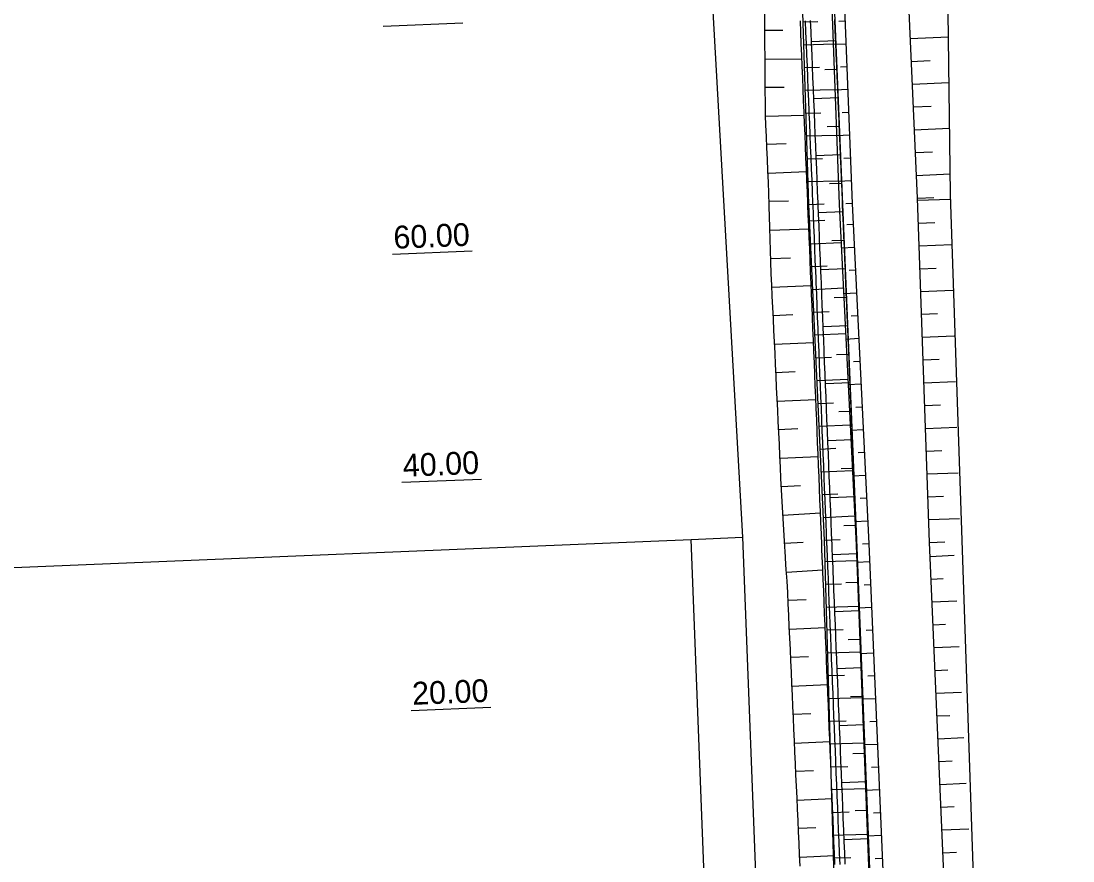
# Model space of a CAD drawing. Extents: x -583721 to -583071, y -1166145 to -1165065.
# Drawn here: x -583294.2 to -583202, y -1165823.5 to -1165749.9 of the extents above; entities that cross this region are included whole.
import ezdxf

# ---------------------------------------------------------------- set-up
doc = ezdxf.new("R2010")
doc.units = 0
for name, color, linetype in [('01_DOPRAVA', 7, 'Continuous'), ('14', 7, 'Continuous'), ('21', 7, 'Continuous'), ('_Rozpiska', 7, 'Continuous'), ('KOTY', 7, 'Continuous'), ('Popis cest', 7, 'Continuous'), ('Popis PP', 7, 'Continuous'), ('Rámy', 7, 'Continuous'), ('Trojúhelniky', 7, 'Continuous')]:
    doc.layers.add(name, color=color, linetype=linetype)

msp = doc.modelspace()

# ---------------------------------------------------------------- linework, layer by layer
at = {"layer": '01_DOPRAVA'}
for p, q in [((-583387, -1165801.65), (-583235.49, -1165795.36)), ((-583235.49, -1165795.36), (-583230.99, -1165795.18))]:
    msp.add_line(p, q, dxfattribs=at)
for points in [[(-583374.25, -1165656.58), (-583351.23, -1165657.59), (-583331.17, -1165652.35), (-583245.16, -1165665.31), (-583236.84, -1165691.62), (-583230.99, -1165795.18)], [(-583228.69, -1165666.2), (-583226.21, -1165672.99), (-583225.84, -1165679.92), (-583220.97, -1165796.08), (-583216.51, -1165909.44), (-583213.19, -1165995.13), (-583203.41, -1165993.97)], [(-583206.76, -1165905.62), (-583208.9, -1165862.71), (-583209.34, -1165848.45), (-583210.45, -1165834.4), (-583212.79, -1165765.14), (-583213.22, -1165730.9), (-583214.03, -1165712.42)], [(-583232.68, -1165868.31), (-583234.23, -1165827.88), (-583235.49, -1165795.36)], [(-583230.99, -1165795.18), (-583226.89, -1165901.72), (-583222.76, -1166003.69), (-583215.5, -1166006.52)]]:
    msp.add_lwpolyline(points, dxfattribs=at)
at = {"layer": '14'}
for p, q in [((-583227.47, -1165750.761), (-583229.042, -1165750.773)), ((-583224.957, -1165751.73), (-583222.833, -1165751.643)), ((-583229.023, -1165753.273), (-583225.796, -1165753.248)), ((-583223.791, -1165754.184), (-583222.728, -1165754.141)), ((-583227.349, -1165755.759), (-583229.004, -1165755.773)), ((-583224.752, -1165756.726), (-583222.624, -1165756.639)), ((-583228.983, -1165758.273), (-583225.594, -1165758.182)), ((-583223.584, -1165759.18), (-583222.519, -1165759.137)), ((-583227.182, -1165760.696), (-583228.87, -1165760.77)), ((-583224.548, -1165761.722), (-583222.414, -1165761.634)), ((-583228.762, -1165763.268), (-583225.391, -1165763.135)), ((-583223.378, -1165764.176), (-583222.309, -1165764.132)), ((-583226.981, -1165765.708), (-583228.674, -1165765.766)), ((-583224.343, -1165766.718), (-583222.205, -1165766.63)), ((-583228.589, -1165768.265), (-583225.185, -1165768.156)), ((-583223.171, -1165769.172), (-583222.1, -1165769.128)), ((-583226.799, -1165770.708), (-583228.515, -1165770.764)), ((-583224.139, -1165771.713), (-583221.995, -1165771.626)), ((-583228.426, -1165773.262), (-583224.982, -1165773.119)), ((-583222.964, -1165774.167), (-583221.891, -1165774.123)), ((-583226.594, -1165775.678), (-583228.308, -1165775.759)), ((-583223.934, -1165776.709), (-583221.786, -1165776.621)), ((-583228.189, -1165778.256), (-583224.778, -1165778.095)), ((-583222.757, -1165779.163), (-583221.681, -1165779.119)), ((-583226.374, -1165780.673), (-583228.071, -1165780.754)), ((-583223.73, -1165781.705), (-583221.576, -1165781.617)), ((-583227.953, -1165783.251), (-583224.574, -1165783.091)), ((-583222.55, -1165784.159), (-583221.472, -1165784.115)), ((-583226.153, -1165785.668), (-583227.834, -1165785.748)), ((-583223.525, -1165786.701), (-583221.367, -1165786.612)), ((-583227.716, -1165788.245), (-583224.369, -1165788.087)), ((-583222.343, -1165789.154), (-583221.262, -1165789.11)), ((-583225.933, -1165790.658), (-583227.598, -1165790.742)), ((-583223.321, -1165791.697), (-583221.157, -1165791.608)), ((-583227.462, -1165793.239), (-583224.166, -1165793.047)), ((-583222.136, -1165794.15), (-583221.053, -1165794.106)), ((-583225.686, -1165795.632), (-583227.307, -1165795.734)), ((-583223.116, -1165796.692), (-583220.949, -1165796.604)), ((-583227.149, -1165798.229), (-583223.962, -1165798.034)), ((-583221.933, -1165799.146), (-583220.851, -1165799.102)), ((-583225.43, -1165800.643), (-583227.002, -1165800.724)), ((-583222.912, -1165801.688), (-583220.753, -1165801.6)), ((-583226.89, -1165803.222), (-583223.755, -1165803.081)), ((-583221.732, -1165804.142), (-583220.655, -1165804.098)), ((-583225.215, -1165805.649), (-583226.777, -1165805.719)), ((-583222.707, -1165806.684), (-583220.556, -1165806.596)), ((-583226.665, -1165808.217), (-583223.551, -1165808.077)), ((-583221.531, -1165809.138), (-583220.458, -1165809.094)), ((-583225.001, -1165810.645), (-583226.553, -1165810.714)), ((-583222.503, -1165811.68), (-583220.36, -1165811.592)), ((-583226.44, -1165813.212), (-583223.346, -1165813.073)), ((-583221.331, -1165814.134), (-583220.261, -1165814.09)), ((-583224.786, -1165815.64), (-583226.328, -1165815.709)), ((-583222.298, -1165816.676), (-583220.163, -1165816.588)), ((-583226.216, -1165818.207), (-583223.142, -1165818.068)), ((-583221.13, -1165819.13), (-583220.065, -1165819.086)), ((-583224.571, -1165820.635), (-583226.103, -1165820.704)), ((-583222.094, -1165821.671), (-583219.967, -1165821.584)), ((-583225.991, -1165823.202), (-583222.937, -1165823.064))]:
    msp.add_line(p, q, dxfattribs=at)
at = {"layer": '21'}
for points in [[(-583225.956, -1165823.988), (-583226.001, -1165822.989), (-583226.045, -1165821.99), (-583226.09, -1165820.991), (-583226.135, -1165819.992), (-583226.18, -1165818.993), (-583226.225, -1165817.994), (-583226.27, -1165816.995), (-583226.315, -1165815.996), (-583226.36, -1165814.997), (-583226.405, -1165813.998), (-583226.45, -1165812.999), (-583226.495, -1165812), (-583226.54, -1165811.001), (-583226.585, -1165810.002), (-583226.63, -1165809.003), (-583226.675, -1165808.004), (-583226.72, -1165807.005), (-583226.765, -1165806.006), (-583226.81, -1165805.007), (-583226.854, -1165804.008), (-583226.899, -1165803.009), (-583226.944, -1165802.01), (-583226.989, -1165801.011), (-583227.034, -1165800.012), (-583227.098, -1165799.014), (-583227.142, -1165798.334), (-583227.162, -1165798.015), (-583227.227, -1165797.017), (-583227.27, -1165796.338), (-583227.284, -1165796.111), (-583227.29, -1165796.019), (-583227.352, -1165795.021), (-583227.414, -1165794.022), (-583227.476, -1165793.024), (-583227.537, -1165792.026), (-583227.584, -1165791.027), (-583227.632, -1165790.028), (-583227.679, -1165789.029), (-583227.726, -1165788.03), (-583227.774, -1165787.031), (-583227.821, -1165786.032), (-583227.868, -1165785.033), (-583227.916, -1165784.035), (-583227.963, -1165783.036), (-583228.01, -1165782.037), (-583228.058, -1165781.038), (-583228.105, -1165780.039), (-583228.152, -1165779.04), (-583228.2, -1165778.041), (-583228.247, -1165777.042), (-583228.294, -1165776.043), (-583228.342, -1165775.044), (-583228.389, -1165774.046), (-583228.436, -1165773.047), (-583228.457, -1165772.604), (-583228.477, -1165772.047), (-583228.506, -1165771.048), (-583228.536, -1165770.048), (-583228.566, -1165769.049), (-583228.596, -1165768.049), (-583228.63, -1165767.05), (-583228.658, -1165766.24), (-583228.664, -1165766.05), (-583228.699, -1165765.051), (-583228.733, -1165764.051), (-583228.77, -1165763.052), (-583228.814, -1165762.053), (-583228.858, -1165761.054), (-583228.902, -1165760.055), (-583228.945, -1165759.056), (-583228.986, -1165758.207), (-583228.987, -1165758.057), (-583228.987, -1165758.031), (-583228.994, -1165757.056), (-583229.002, -1165756.056), (-583229.01, -1165755.055), (-583229.017, -1165754.055), (-583229.025, -1165753.054), (-583229.032, -1165752.053), (-583229.04, -1165751.053), (-583229.047, -1165750.052), (-583229.055, -1165749.052)], [(-583219.882, -1165823.739), (-583219.921, -1165822.74), (-583219.96, -1165821.741), (-583220, -1165820.741), (-583220.039, -1165819.742), (-583220.078, -1165818.743), (-583220.118, -1165817.744), (-583220.157, -1165816.745), (-583220.196, -1165815.745), (-583220.236, -1165814.746), (-583220.275, -1165813.747), (-583220.314, -1165812.748), (-583220.354, -1165811.748), (-583220.393, -1165810.749), (-583220.432, -1165809.75), (-583220.471, -1165808.751), (-583220.511, -1165807.752), (-583220.55, -1165806.752), (-583220.589, -1165805.753), (-583220.629, -1165804.754), (-583220.668, -1165803.755), (-583220.707, -1165802.755), (-583220.747, -1165801.756), (-583220.786, -1165800.757), (-583220.825, -1165799.758), (-583220.865, -1165798.758), (-583220.891, -1165798.079), (-583220.904, -1165797.759), (-583220.943, -1165796.76), (-583220.97, -1165796.08), (-583220.98, -1165795.853), (-583220.983, -1165795.761), (-583221.025, -1165794.762), (-583221.067, -1165793.763), (-583221.109, -1165792.763), (-583221.151, -1165791.764), (-583221.193, -1165790.765), (-583221.235, -1165789.766), (-583221.277, -1165788.767), (-583221.318, -1165787.768), (-583221.36, -1165786.769), (-583221.402, -1165785.77), (-583221.444, -1165784.77), (-583221.486, -1165783.771), (-583221.528, -1165782.772), (-583221.57, -1165781.773), (-583221.612, -1165780.774), (-583221.654, -1165779.775), (-583221.695, -1165778.776), (-583221.737, -1165777.777), (-583221.779, -1165776.777), (-583221.821, -1165775.778), (-583221.863, -1165774.779), (-583221.905, -1165773.78), (-583221.947, -1165772.781), (-583221.965, -1165772.338), (-583221.989, -1165771.782), (-583222.031, -1165770.783), (-583222.072, -1165769.784), (-583222.114, -1165768.784), (-583222.156, -1165767.785), (-583222.198, -1165766.786), (-583222.232, -1165765.977), (-583222.24, -1165765.787), (-583222.282, -1165764.788), (-583222.324, -1165763.789), (-583222.366, -1165762.79), (-583222.408, -1165761.791), (-583222.449, -1165760.792), (-583222.491, -1165759.792), (-583222.533, -1165758.793), (-583222.569, -1165757.945), (-583222.575, -1165757.794), (-583222.576, -1165757.769), (-583222.617, -1165756.795), (-583222.659, -1165755.796), (-583222.701, -1165754.797), (-583222.743, -1165753.798), (-583222.785, -1165752.799), (-583222.826, -1165751.799), (-583222.868, -1165750.8), (-583222.91, -1165749.801)], [(-583222.905, -1165823.863), (-583222.946, -1165822.864), (-583222.986, -1165821.865), (-583223.027, -1165820.865), (-583223.068, -1165819.866), (-583223.109, -1165818.867), (-583223.15, -1165817.868), (-583223.191, -1165816.869), (-583223.232, -1165815.87), (-583223.273, -1165814.87), (-583223.314, -1165813.871), (-583223.355, -1165812.872), (-583223.396, -1165811.873), (-583223.436, -1165810.874), (-583223.477, -1165809.875), (-583223.518, -1165808.875), (-583223.559, -1165807.876), (-583223.6, -1165806.877), (-583223.641, -1165805.878), (-583223.682, -1165804.879), (-583223.723, -1165803.88), (-583223.764, -1165802.88), (-583223.805, -1165801.881), (-583223.845, -1165800.882), (-583223.886, -1165799.883), (-583223.927, -1165798.884), (-583223.955, -1165798.204), (-583223.968, -1165797.885), (-583224.009, -1165796.886), (-583224.037, -1165796.206), (-583224.046, -1165795.979), (-583224.05, -1165795.886), (-583224.091, -1165794.887), (-583224.132, -1165793.888), (-583224.173, -1165792.889), (-583224.214, -1165791.89), (-583224.255, -1165790.891), (-583224.295, -1165789.891), (-583224.336, -1165788.892), (-583224.377, -1165787.893), (-583224.418, -1165786.894), (-583224.459, -1165785.895), (-583224.5, -1165784.896), (-583224.541, -1165783.896), (-583224.582, -1165782.897), (-583224.623, -1165781.898), (-583224.664, -1165780.899), (-583224.704, -1165779.9), (-583224.745, -1165778.901), (-583224.786, -1165777.901), (-583224.827, -1165776.902), (-583224.868, -1165775.903), (-583224.909, -1165774.904), (-583224.95, -1165773.905), (-583224.991, -1165772.906), (-583225.009, -1165772.463), (-583225.032, -1165771.906), (-583225.073, -1165770.907), (-583225.113, -1165769.908), (-583225.154, -1165768.909), (-583225.195, -1165767.91), (-583225.236, -1165766.911), (-583225.269, -1165766.102), (-583225.277, -1165765.911), (-583225.318, -1165764.912), (-583225.359, -1165763.913), (-583225.4, -1165762.914), (-583225.441, -1165761.915), (-583225.482, -1165760.916), (-583225.523, -1165759.916), (-583225.563, -1165758.917), (-583225.598, -1165758.069), (-583225.604, -1165757.918), (-583225.605, -1165757.893), (-583225.645, -1165756.919), (-583225.686, -1165755.92), (-583225.727, -1165754.921), (-583225.768, -1165753.922), (-583225.809, -1165752.922), (-583225.85, -1165751.923), (-583225.891, -1165750.924), (-583225.932, -1165749.925)], [(-583222.005, -1165823.826), (-583222.046, -1165822.827), (-583222.087, -1165821.828), (-583222.128, -1165820.829), (-583222.169, -1165819.829), (-583222.21, -1165818.83), (-583222.251, -1165817.831), (-583222.292, -1165816.832), (-583222.333, -1165815.833), (-583222.374, -1165814.834), (-583222.414, -1165813.834), (-583222.455, -1165812.835), (-583222.496, -1165811.836), (-583222.537, -1165810.837), (-583222.578, -1165809.838), (-583222.619, -1165808.839), (-583222.66, -1165807.839), (-583222.701, -1165806.84), (-583222.742, -1165805.841), (-583222.783, -1165804.842), (-583222.824, -1165803.843), (-583222.864, -1165802.844), (-583222.905, -1165801.845), (-583222.946, -1165800.845), (-583222.987, -1165799.846), (-583223.028, -1165798.847), (-583223.056, -1165798.167), (-583223.069, -1165797.848), (-583223.11, -1165796.849), (-583223.138, -1165796.169), (-583223.147, -1165795.942), (-583223.151, -1165795.85), (-583223.192, -1165794.85), (-583223.233, -1165793.851), (-583223.273, -1165792.852), (-583223.314, -1165791.853), (-583223.355, -1165790.854), (-583223.396, -1165789.855), (-583223.437, -1165788.855), (-583223.478, -1165787.856), (-583223.519, -1165786.857), (-583223.56, -1165785.858), (-583223.601, -1165784.859), (-583223.642, -1165783.86), (-583223.682, -1165782.86), (-583223.723, -1165781.861), (-583223.764, -1165780.862), (-583223.805, -1165779.863), (-583223.846, -1165778.864), (-583223.887, -1165777.865), (-583223.928, -1165776.865), (-583223.969, -1165775.866), (-583224.01, -1165774.867), (-583224.051, -1165773.868), (-583224.092, -1165772.869), (-583224.11, -1165772.426), (-583224.132, -1165771.87), (-583224.173, -1165770.87), (-583224.214, -1165769.871), (-583224.255, -1165768.872), (-583224.296, -1165767.873), (-583224.337, -1165766.874), (-583224.37, -1165766.065), (-583224.378, -1165765.875), (-583224.419, -1165764.875), (-583224.46, -1165763.876), (-583224.501, -1165762.877), (-583224.541, -1165761.878), (-583224.582, -1165760.879), (-583224.623, -1165759.88), (-583224.664, -1165758.881), (-583224.699, -1165758.032), (-583224.705, -1165757.881), (-583224.706, -1165757.856), (-583224.746, -1165756.882), (-583224.787, -1165755.883), (-583224.828, -1165754.884), (-583224.869, -1165753.885), (-583224.91, -1165752.886), (-583224.951, -1165751.886), (-583224.991, -1165750.887), (-583225.032, -1165749.888)]]:
    msp.add_lwpolyline(points, dxfattribs=at)
at = {"layer": '_Rozpiska'}
for points in [[(-583225.68, -1165750.02), (-583224.4, -1165749.98)], [(-583222.01, -1165749.95), (-583222.57, -1165749.97)], [(-583216.3, -1165751.47), (-583212.96, -1165751.33)], [(-583225.62, -1165752.02), (-583223.05, -1165751.94)], [(-583221.94, -1165751.95), (-583223.04, -1165751.99)], [(-583216.21, -1165753.47), (-583214.57, -1165753.4)], [(-583225.55, -1165754.02), (-583224.26, -1165753.98)], [(-583221.86, -1165753.95), (-583222.41, -1165753.97)], [(-583216.12, -1165755.47), (-583212.91, -1165755.33)], [(-583225.49, -1165756.01), (-583222.9, -1165755.93)], [(-583221.78, -1165755.95), (-583222.89, -1165755.99)], [(-583225.43, -1165758.01), (-583224.13, -1165757.97)], [(-583221.7, -1165757.95), (-583222.26, -1165757.97)], [(-583216.03, -1165757.47), (-583214.46, -1165757.4)], [(-583225.37, -1165760.01), (-583222.75, -1165759.93)], [(-583221.62, -1165759.94), (-583222.74, -1165759.99)], [(-583215.95, -1165759.47), (-583212.86, -1165759.33)], [(-583215.86, -1165761.46), (-583214.35, -1165761.4)], [(-583225.3, -1165762.01), (-583223.99, -1165761.97)], [(-583221.55, -1165761.94), (-583222.11, -1165761.97)], [(-583215.77, -1165763.46), (-583212.81, -1165763.33)], [(-583225.24, -1165764.01), (-583222.6, -1165763.93)], [(-583221.47, -1165763.94), (-583222.59, -1165763.99)], [(-583215.68, -1165765.46), (-583214.23, -1165765.4)], [(-583225.18, -1165766.01), (-583223.85, -1165765.97)], [(-583221.39, -1165765.94), (-583221.96, -1165765.96)], [(-583215.67, -1165765.64), (-583212.78, -1165765.54)], [(-583225.11, -1165767.46), (-583223.78, -1165767.4)], [(-583221.3, -1165767.78), (-583221.86, -1165767.81)], [(-583215.6, -1165767.64), (-583214.16, -1165767.59)], [(-583225.02, -1165769.46), (-583222.36, -1165769.33)], [(-583221.2, -1165769.78), (-583222.33, -1165769.84)], [(-583215.53, -1165769.64), (-583212.67, -1165769.53)], [(-583224.93, -1165771.46), (-583223.59, -1165771.39)], [(-583221.1, -1165771.78), (-583221.67, -1165771.81)], [(-583215.46, -1165771.64), (-583214.04, -1165771.58)], [(-583224.84, -1165773.45), (-583222.16, -1165773.33)], [(-583221, -1165773.78), (-583222.13, -1165773.83)], [(-583215.39, -1165773.63), (-583212.56, -1165773.53)], [(-583224.75, -1165775.45), (-583223.4, -1165775.39)], [(-583215.32, -1165775.63), (-583213.91, -1165775.58)], [(-583220.91, -1165775.77), (-583221.47, -1165775.8)], [(-583224.66, -1165777.45), (-583221.96, -1165777.33)], [(-583220.81, -1165777.77), (-583221.94, -1165777.83)], [(-583215.25, -1165777.63), (-583212.45, -1165777.53)], [(-583224.56, -1165779.45), (-583223.21, -1165779.38)], [(-583220.71, -1165779.77), (-583221.27, -1165779.8)], [(-583215.18, -1165779.63), (-583213.78, -1165779.58)], [(-583224.47, -1165781.44), (-583221.77, -1165781.32)], [(-583220.61, -1165781.77), (-583221.74, -1165781.82)], [(-583215.11, -1165781.63), (-583212.34, -1165781.53)], [(-583224.38, -1165783.44), (-583223.02, -1165783.38)], [(-583220.51, -1165783.76), (-583221.08, -1165783.79)], [(-583215.04, -1165783.63), (-583213.66, -1165783.58)], [(-583224.29, -1165785.44), (-583221.57, -1165785.32)], [(-583220.41, -1165785.76), (-583221.54, -1165785.82)], [(-583214.96, -1165785.63), (-583212.22, -1165785.53)], [(-583224.2, -1165787.44), (-583222.83, -1165787.38)], [(-583214.89, -1165787.63), (-583213.53, -1165787.58)], [(-583220.31, -1165787.76), (-583220.88, -1165787.79)], [(-583224.11, -1165789.44), (-583221.37, -1165789.31)], [(-583220.22, -1165789.76), (-583221.35, -1165789.81)], [(-583214.82, -1165789.62), (-583212.11, -1165789.53)], [(-583224.01, -1165791.43), (-583222.64, -1165791.37)], [(-583220.12, -1165791.75), (-583220.68, -1165791.78)], [(-583214.75, -1165791.62), (-583213.4, -1165791.57)], [(-583223.92, -1165793.43), (-583221.18, -1165793.31)], [(-583220.02, -1165793.75), (-583221.15, -1165793.81)], [(-583214.68, -1165793.62), (-583212, -1165793.53)], [(-583223.83, -1165795.43), (-583222.45, -1165795.37)], [(-583219.92, -1165795.75), (-583220.49, -1165795.78)], [(-583214.61, -1165795.62), (-583213.28, -1165795.57)], [(-583214.56, -1165796.85), (-583212.45, -1165796.75)], [(-583223.78, -1165797.3), (-583221, -1165797.22)], [(-583219.85, -1165797.33), (-583220.99, -1165797.38)], [(-583223.72, -1165799.29), (-583222.32, -1165799.25)], [(-583219.77, -1165799.33), (-583220.34, -1165799.36)], [(-583214.47, -1165798.84), (-583213.41, -1165798.8)], [(-583223.66, -1165801.29), (-583220.84, -1165801.21)], [(-583219.68, -1165801.33), (-583220.84, -1165801.38)], [(-583214.38, -1165800.84), (-583212.23, -1165800.75)], [(-583223.6, -1165803.29), (-583222.19, -1165803.25)], [(-583214.3, -1165802.84), (-583213.21, -1165802.79)], [(-583219.6, -1165803.33), (-583220.18, -1165803.35)], [(-583214.21, -1165804.84), (-583212.02, -1165804.74)], [(-583223.55, -1165805.29), (-583220.69, -1165805.21)], [(-583219.51, -1165805.33), (-583220.68, -1165805.38)], [(-583214.13, -1165806.84), (-583213.02, -1165806.79)], [(-583223.49, -1165807.29), (-583222.05, -1165807.25)], [(-583219.43, -1165807.33), (-583220.02, -1165807.35)], [(-583214.04, -1165808.83), (-583211.81, -1165808.74)], [(-583223.43, -1165809.29), (-583220.54, -1165809.21)], [(-583219.34, -1165809.32), (-583220.53, -1165809.37)], [(-583223.37, -1165811.29), (-583221.92, -1165811.25)], [(-583219.25, -1165811.32), (-583219.85, -1165811.35)], [(-583213.95, -1165810.83), (-583212.83, -1165810.78)], [(-583223.31, -1165813.29), (-583220.38, -1165813.2)], [(-583219.17, -1165813.32), (-583220.38, -1165813.37)], [(-583213.87, -1165812.83), (-583211.6, -1165812.73)], [(-583223.26, -1165815.29), (-583221.78, -1165815.25)], [(-583213.78, -1165814.83), (-583212.64, -1165814.78)], [(-583219.08, -1165815.32), (-583219.69, -1165815.34)], [(-583213.7, -1165816.83), (-583211.39, -1165816.73)], [(-583223.2, -1165817.29), (-583220.23, -1165817.2)], [(-583219, -1165817.32), (-583220.22, -1165817.37)], [(-583213.61, -1165818.82), (-583212.45, -1165818.77)], [(-583223.14, -1165819.29), (-583221.65, -1165819.24)], [(-583218.91, -1165819.31), (-583219.53, -1165819.34)], [(-583213.52, -1165820.82), (-583211.18, -1165820.72)], [(-583223.08, -1165821.29), (-583220.08, -1165821.2)], [(-583218.83, -1165821.31), (-583220.07, -1165821.37)], [(-583223.03, -1165823.28), (-583221.51, -1165823.24)], [(-583218.74, -1165823.31), (-583219.37, -1165823.34)], [(-583213.44, -1165822.82), (-583212.25, -1165822.77)]]:
    msp.add_lwpolyline(points, dxfattribs=at)
at = {"layer": 'KOTY'}
msp.add_lwpolyline([(-583222.455, -1165823.845), (-583222.496, -1165822.845), (-583222.537, -1165821.846), (-583222.578, -1165820.847), (-583222.619, -1165819.848), (-583222.66, -1165818.849), (-583222.7, -1165817.85), (-583222.741, -1165816.85), (-583222.782, -1165815.851), (-583222.823, -1165814.852), (-583222.864, -1165813.853), (-583222.905, -1165812.854), (-583222.946, -1165811.855), (-583222.987, -1165810.855), (-583223.028, -1165809.856), (-583223.069, -1165808.857), (-583223.11, -1165807.858), (-583223.15, -1165806.859), (-583223.191, -1165805.86), (-583223.232, -1165804.86), (-583223.273, -1165803.861), (-583223.314, -1165802.862), (-583223.355, -1165801.863), (-583223.396, -1165800.864), (-583223.437, -1165799.865), (-583223.478, -1165798.865), (-583223.505, -1165798.186), (-583223.519, -1165797.866), (-583223.559, -1165796.867), (-583223.587, -1165796.187), (-583223.597, -1165795.96), (-583223.6, -1165795.868), (-583223.641, -1165794.869), (-583223.682, -1165793.87), (-583223.723, -1165792.87), (-583223.764, -1165791.871), (-583223.805, -1165790.872), (-583223.846, -1165789.873), (-583223.887, -1165788.874), (-583223.928, -1165787.875), (-583223.969, -1165786.875), (-583224.009, -1165785.876), (-583224.05, -1165784.877), (-583224.091, -1165783.878), (-583224.132, -1165782.879), (-583224.173, -1165781.88), (-583224.214, -1165780.88), (-583224.255, -1165779.881), (-583224.296, -1165778.882), (-583224.337, -1165777.883), (-583224.378, -1165776.884), (-583224.418, -1165775.885), (-583224.459, -1165774.886), (-583224.5, -1165773.886), (-583224.541, -1165772.887), (-583224.559, -1165772.445), (-583224.582, -1165771.888), (-583224.623, -1165770.889), (-583224.664, -1165769.89), (-583224.705, -1165768.891), (-583224.746, -1165767.891), (-583224.787, -1165766.892), (-583224.82, -1165766.083), (-583224.827, -1165765.893), (-583224.868, -1165764.894), (-583224.909, -1165763.895), (-583224.95, -1165762.896), (-583224.991, -1165761.896), (-583225.032, -1165760.897), (-583225.073, -1165759.898), (-583225.114, -1165758.899), (-583225.149, -1165758.05), (-583225.155, -1165757.9), (-583225.156, -1165757.874), (-583225.196, -1165756.901), (-583225.237, -1165755.901), (-583225.277, -1165754.902), (-583225.318, -1165753.903), (-583225.359, -1165752.904), (-583225.4, -1165751.905), (-583225.441, -1165750.906), (-583225.482, -1165749.906)], dxfattribs=at)
at = {"layer": 'Popis cest'}
for points in [[(-583214.565, -1166024.741), (-583215.84, -1165999.86), (-583216.56, -1165980.47), (-583218.74, -1165935.28), (-583219.93, -1165903.85), (-583222.02, -1165858.12), (-583222.68, -1165835.28), (-583223.83, -1165795.43), (-583225.18, -1165766.01), (-583226.29, -1165730.41), (-583226.47, -1165703.12), (-583228.25, -1165673.5)], [(-583202.046, -1166023.279), (-583203.28, -1165999.31), (-583203.79, -1165978.24), (-583205.99, -1165934.1), (-583206.83, -1165909.26), (-583206.76, -1165905.62), (-583208.9, -1165862.71), (-583209.34, -1165848.45), (-583210.45, -1165834.4), (-583212.79, -1165765.14), (-583213.22, -1165730.9), (-583214.43, -1165703.46)]]:
    msp.add_lwpolyline(points, dxfattribs=at)
at = {"layer": 'Popis PP'}
for points in [[(-583205.384, -1166023.669), (-583206.37, -1165999.45), (-583206.99, -1165978.09), (-583208.8, -1165934.4), (-583209.98, -1165909.96), (-583210.18, -1165905.46), (-583211.89, -1165862.15), (-583212.92, -1165834.81), (-583214.61, -1165795.62), (-583215.68, -1165765.46), (-583217.22, -1165730.71), (-583218.84, -1165703.6), (-583219.86, -1165675.86), (-583220.15, -1165659.61)], [(-583225.03, -1165669.36), (-583224.72, -1165676.77), (-583223.57, -1165703.33), (-583222.76, -1165730.88), (-583221.39, -1165765.94), (-583219.92, -1165795.75), (-583218.23, -1165835.3), (-583217.57, -1165858.89), (-583215.65, -1165904.71), (-583214.33, -1165934.9), (-583212.44, -1165979.07), (-583211.41, -1165999.47), (-583210.642, -1166024.283)]]:
    msp.add_lwpolyline(points, dxfattribs=at)
at = {"layer": 'Rámy'}
msp.add_lwpolyline([(-583225.84, -1165679.92), (-583224.89, -1165703.34), (-583223.84, -1165730.71), (-583222.52, -1165765.99), (-583221.05, -1165795.86), (-583219.53, -1165835.39), (-583218.74, -1165858.37), (-583216.69, -1165904.53), (-583215.95, -1165934.96), (-583213.79, -1165980.28), (-583213.02, -1165999.42)], dxfattribs=at)
at = {"layer": 'Trojúhelniky'}
for p, q in [((-583255.498, -1165750.134), (-583262.492, -1165750.421)), ((-583254.68, -1165770.118), (-583261.674, -1165770.404)), ((-583253.862, -1165790.101), (-583260.856, -1165790.387)), ((-583253.044, -1165810.084), (-583260.038, -1165810.371))]:
    msp.add_line(p, q, dxfattribs=at)

# ---------------------------------------------------------------- texts
for s, p in [('60.00', (-583261.55, -1165769.898)), ('40.00', (-583260.731, -1165789.882)), ('20.00', (-583259.913, -1165809.865))]:
    msp.add_text(s, height=2, rotation=2.3443, dxfattribs=at).set_placement(p)

doc.saveas('drawing.dxf')
